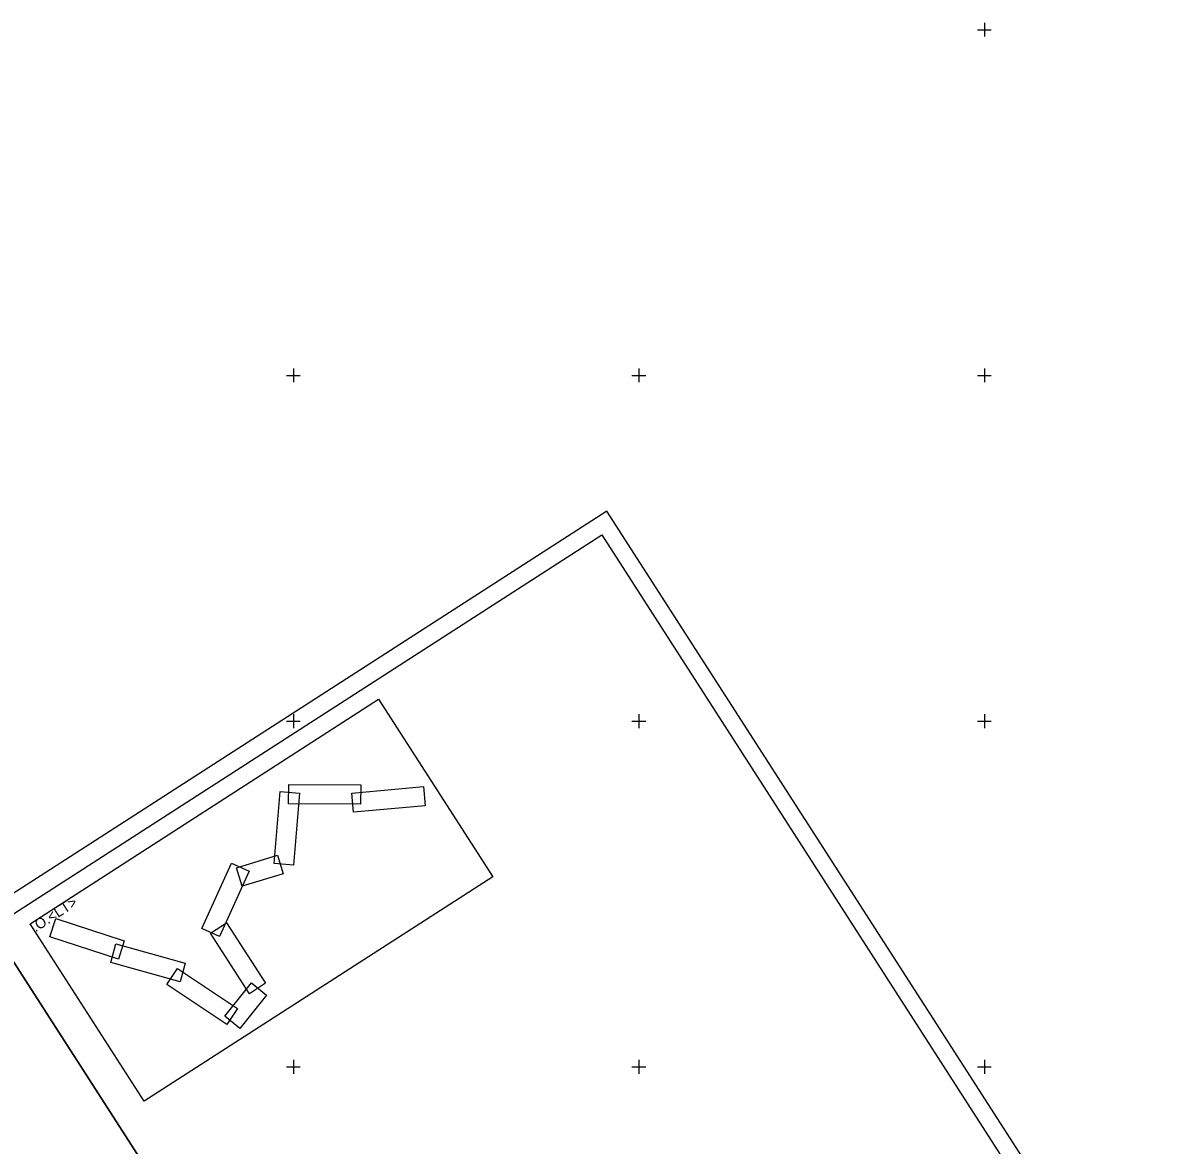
# Model space of a CAD drawing. Extents: x -866402 to -860377, y -1041908 to -1038598.
# Drawn here: x -863478.3 to -863148.5, y -1039622.7 to -1039298 of the extents above; entities that cross this region are included whole.
import ezdxf

# ---------------------------------------------------------------- set-up
doc = ezdxf.new("R2010")
doc.units = 0
for name, color, linetype in [('Vrstva 1', 7, 'Continuous'), ('Vrstva 21', 7, 'Continuous'), ('Vrstva 5', 7, 'Continuous')]:
    doc.layers.add(name, color=color, linetype=linetype)

msp = doc.modelspace()

# ---------------------------------------------------------------- linework, layer by layer
at = {"layer": 'Vrstva 1'}
for points in [[(-864208, -1040370.93), (-863148.52, -1039688.97), (-863309.26, -1039439.25), (-864368.75, -1040121.2)], [(-864361.83, -1040122.7), (-863310.76, -1039446.16), (-863155.43, -1039687.48), (-864206.5, -1040364.02)], [(-864205.01, -1040357.12), (-863334.71, -1039796.93), (-863484.63, -1039564.01), (-864354.93, -1040124.19)], [(-864354.93, -1040124.19), (-863484.63, -1039564.01), (-863334.71, -1039796.93), (-864205.01, -1040357.12)]]:
    msp.add_lwpolyline(points, close=True, dxfattribs=at)
at = {"layer": 'Vrstva 21'}
for points in [[(-863443.16, -1039609.98), (-863476.23, -1039558.6), (-863375.33, -1039493.65), (-863342.26, -1039545.03)], [(-863401.37, -1039523.96), (-863401.35, -1039518.38), (-863380.5, -1039518.48), (-863380.53, -1039524.06)], [(-863382.61, -1039526.37), (-863383.11, -1039520.82), (-863362.35, -1039518.95), (-863361.84, -1039524.5)], [(-863399.97, -1039541.63), (-863405.53, -1039541.17), (-863403.81, -1039520.39), (-863398.25, -1039520.85)], [(-863414.84, -1039547.75), (-863416.46, -1039542.41), (-863404.6, -1039538.82), (-863402.99, -1039544.16)], [(-863421.43, -1039562.33), (-863426.51, -1039560.02), (-863417.88, -1039541.05), (-863412.8, -1039543.36)], [(-863470.49, -1039562.39), (-863468.75, -1039557.09), (-863448.94, -1039563.57), (-863450.67, -1039568.87)], [(-863470.49, -1039562.39), (-863468.75, -1039557.09), (-863448.94, -1039563.57), (-863450.67, -1039568.87)], [(-863408.04, -1039575.85), (-863412.73, -1039578.87), (-863424.02, -1039561.34), (-863419.32, -1039558.32)], [(-863452.88, -1039569.8), (-863451.38, -1039564.43), (-863431.3, -1039570.02), (-863432.79, -1039575.39)], [(-863436.62, -1039576.18), (-863433.51, -1039571.55), (-863416.19, -1039583.16), (-863419.3, -1039587.79)], [(-863415.53, -1039588.89), (-863419.88, -1039585.39), (-863412.12, -1039575.74), (-863407.77, -1039579.24)]]:
    msp.add_lwpolyline(points, close=True, dxfattribs=at)
at = {"layer": 'Vrstva 5'}
for p, q in [((-863200, -1039298), (-863200, -1039302)), ((-863202, -1039300), (-863198, -1039300)), ((-863402, -1039400), (-863398, -1039400)), ((-863400, -1039398), (-863400, -1039402)), ((-863302, -1039400), (-863298, -1039400)), ((-863300, -1039398), (-863300, -1039402)), ((-863202, -1039400), (-863198, -1039400)), ((-863200, -1039398), (-863200, -1039402)), ((-863402, -1039500), (-863398, -1039500)), ((-863400, -1039498), (-863400, -1039502)), ((-863302, -1039500), (-863298, -1039500)), ((-863300, -1039498), (-863300, -1039502)), ((-863202, -1039500), (-863198, -1039500)), ((-863200, -1039498), (-863200, -1039502)), ((-863400, -1039598), (-863400, -1039602)), ((-863300, -1039598), (-863300, -1039602)), ((-863200, -1039598), (-863200, -1039602)), ((-863402, -1039600), (-863398, -1039600)), ((-863302, -1039600), (-863298, -1039600)), ((-863202, -1039600), (-863198, -1039600))]:
    msp.add_line(p, q, dxfattribs=at)

# ---------------------------------------------------------------- texts
at = {"layer": 'Vrstva 1'}
msp.add_text('.O.<LT>', height=3, rotation=32.768, dxfattribs=at).set_placement((-863474.61, -1039561.12))

doc.saveas('drawing.dxf')
